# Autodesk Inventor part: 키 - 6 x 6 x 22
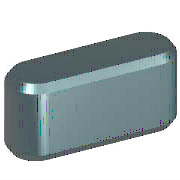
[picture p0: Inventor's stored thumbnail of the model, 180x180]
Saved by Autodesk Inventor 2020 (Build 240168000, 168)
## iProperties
Created: 2012-02
Part Number: 키 - 6 x 6 x 22
Material: 강철, 연강
Description: 키 및 해당 키홈
Document SubType Name: Modeling
Standard: KS B 1311
Designer: mduedu
Standards Organization: KS
Language: ko-KR
Size Designation: 6 x 6 x 22
Categories: <MemberInstance><Categories><Category DisplayName="샤프트 부품" InternalName="7f7aeb1f-a693-4053-b835-cee3144e0d98" Mnemonic="SHFT"><Category DisplayName="키" Interna
Density: 7.86 g/cm^3
Mass: 5.79788 g
Surface Area: 5.294 cm^2
Volume: 0.737644 cm^3
Appearance: 노란색
IsCustomPart: 1
Author: mduedu
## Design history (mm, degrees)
workplane "Work Plane1"
workplane "Work Plane2"
sketch "스케치1"
  geometry: L1 (3, 3)-(19, 3); L2 (19, -3)-(3, -3); L3 (0, 9.4)-(0, -7.4) reference; L4 (-5, 0)-(30, 0) reference; L5 (22, 0)-(22, 7); A1 r 3 centre (3, 0) between (3, 3) and (3, -3); A2 r 3 centre (19, 0) between (19, -3) and (19, 3)
  constraints: 6 end point, 5 point on circle, 4 tangent, 3 point on line, 2 centre point, 1 horizontal, 1 parallel, 1 perpendicular
  dimensions: "d0" = 3 radius of A1 (= 0.5 x PB); "d13" = 3 radius of A2 (= 0.5 x PB); "d14" = 22 distance between parallel lines of L5 L3 (= NLG)
extrude "본체1" new body sketch "스케치1" taper "d3" = 0 deg; stored distance "d4" = 10
workplane "Work Plane3"
body "Solid1"
chamfer "모따기1" distance "d8" = 0.4 (= PHH); stored, may be unused: second distance "d9" = 0.4 (= PHH), angle "d15" = 45 deg
other parameters: "d1" = -3.5 (= -PNT), "d2" = 2.5 (= PH - PNT), "NLG" = 22 [user parameter; used in 3 equation terms], "PB" = 6 [user parameter; used in 2 equation terms], "PNT" = 3.5 [user parameter; used in 2 equation terms], "PH" = 6 [user parameter; used in 1 equation term], "PHH" = 0.4 [user parameter; used in 2 equation terms], "d10" = 0, "d16" = 0, "d17" = 0, "d18" = 0, "WDMIN" = 17 [user parameter], "PLB2" = 22 (= NLG) [user parameter], "WDMAX" = 22 [user parameter], "PLB1" = 22 (= NLG) [user parameter], "RR" = 0.16 [user parameter], "PUEB" = 2.8 [user parameter]
